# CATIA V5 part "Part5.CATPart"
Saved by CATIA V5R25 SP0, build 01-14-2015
Part number: Part5
Bounding box of the stored display mesh (mm): x -12.5 to 12.5, y -2.5 to 2.5, z -2.462 to 2.462
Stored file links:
  D:\1kinematik uygulama-1-03112025\Part5.CATPart
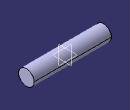
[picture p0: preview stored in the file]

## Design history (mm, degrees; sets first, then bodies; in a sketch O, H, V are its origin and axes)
Body1 (main body)
  Sketch1 on yz-plane, origin (0, 0, 0), H (0, 1, 0), V (0, 0, 1)
    circle A1 centre (0, 0) radius 2.5
    radius A1 = 2.5
  Pad1: profile Sketch1, direction (1, 0, 0), length 12.5, mirrored extent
